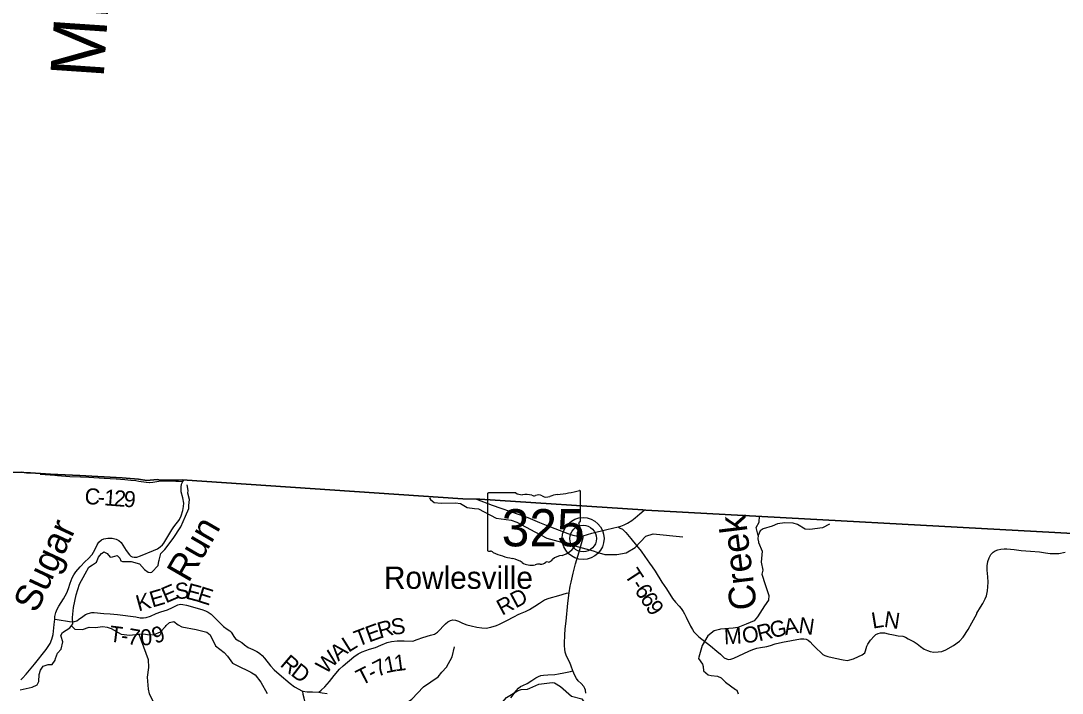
# Model space of a CAD drawing. Extents: x 1878108 to 2183446, y 146837 to 508383.
# Drawn here: x 2019382 to 2038879, y 364937 to 377520 of the extents above; entities that cross this region are included whole.
import ezdxf

# ---------------------------------------------------------------- set-up
doc = ezdxf.new("R2010")
doc.units = 0
for name, color, linetype in [('GM_X_Adjacent_County', 7, 'Continuous'), ('GM_X_Adjacent_County_Text', 7, 'Continuous'), ('GM_X_County', 7, 'Continuous'), ('GM_X_County_Road', 7, 'Continuous'), ('GM_X_County_Road_Text', 7, 'Continuous'), ('GM_X_Minor_River', 7, 'Continuous'), ('GM_X_Minor_River_Text', 7, 'Continuous'), ('GM_X_State_Location', 7, 'Continuous'), ('GM_X_State_Route', 7, 'Continuous'), ('GM_X_State_Shield', 7, 'Continuous'), ('GM_X_Township', 7, 'Continuous'), ('GM_X_Township_Road', 7, 'Continuous'), ('GM_X_Township_Road_Text', 7, 'Continuous'), ('GM_X_Unincorporated', 7, 'Continuous'), ('GM_X_Unincorporated_Location', 7, 'Continuous'), ('GM_X_Unincorporated_Text', 7, 'Continuous')]:
    doc.layers.add(name, color=color, linetype=linetype)

msp = doc.modelspace()

# ---------------------------------------------------------------- linework, layer by layer
at = {"layer": 'GM_X_Adjacent_County'}
msp.add_lwpolyline([(2039539, 367898), (2031084, 368365), (2031027, 368369), (2027978, 368566), (2027659, 368574), (2022405, 368932), (2022089, 368925), (2021996, 368922), (2021936, 368934), (2021744, 368917), (2021587, 368942), (2021277, 368968), (2020487, 369014), (2019939, 369039), (2019751, 369047), (2019564, 369063), (2019490, 369063), (2019394, 369075), (2018544, 369044)], dxfattribs=at)
at = {"layer": 'GM_X_County'}
msp.add_lwpolyline([(2018544, 369044), (2019394, 369075), (2019490, 369063), (2019564, 369063), (2019751, 369047), (2019939, 369039), (2020487, 369014), (2021277, 368968), (2021587, 368942), (2021744, 368917), (2021936, 368934), (2021996, 368922), (2022089, 368925), (2022405, 368932), (2027659, 368574), (2027978, 368566), (2031027, 368369), (2031084, 368365), (2039539, 367898)], dxfattribs=at)
at = {"layer": 'GM_X_County_Road'}
for points in [[(2019746, 369036), (2019930, 369022), (2020016, 369015), (2020069, 369011)], [(2020069, 369011), (2020301, 368994), (2020496, 368986), (2020657, 368979), (2020945, 368964), (2021167, 368947), (2021249, 368941), (2021330, 368934), (2021444, 368924), (2021532, 368915), (2021592, 368907), (2021731, 368884), (2021794, 368880), (2021797, 368881), (2021854, 368888), (2021964, 368904), (2022007, 368910), (2022091, 368912)], [(2022091, 368912), (2022094, 368912), (2022283, 368906), (2022286, 368906), (2022336, 368908), (2022414, 368900)], [(2029963, 364936), (2029955, 364991), (2029942, 365027), (2029920, 365065), (2029874, 365116), (2029818, 365168), (2029786, 365213), (2029754, 365267), (2029719, 365355), (2029687, 365442), (2029660, 365512), (2029622, 365582), (2029590, 365648), (2029573, 365706), (2029565, 365760), (2029561, 365825), (2029561, 365874), (2029565, 366025), (2029575, 366140), (2029592, 366287), (2029626, 366621), (2029648, 366813), (2029669, 366937), (2029685, 367016), (2029725, 367181), (2029768, 367361), (2029834, 367585), (2029910, 367852), (2029910, 367883)]]:
    msp.add_lwpolyline(points, dxfattribs=at)
at = {"layer": 'GM_X_Minor_River'}
for points in [[(2019368, 364997), (2019596, 365051), (2019686, 365094), (2019716, 365156), (2019725, 365284), (2019747, 365365), (2019803, 365443), (2019893, 365475), (2019969, 365473), (2020027, 365552), (2020033, 365586), (2020071, 365684), (2020137, 365762), (2020169, 365895), (2020135, 365999), (2020133, 366015), (2020161, 366073), (2020302, 366160), (2020356, 366238), (2020350, 366353), (2020366, 366543), (2020416, 366778), (2020480, 366975), (2020587, 367171), (2020655, 367294), (2020725, 367340), (2020801, 367389), (2020833, 367483), (2020891, 367551), (2020905, 367559), (2020937, 367581), (2021001, 367553), (2021057, 367481), (2021101, 367487), (2021185, 367512), (2021235, 367467), (2021257, 367415), (2021285, 367403), (2021449, 367404), (2021601, 367358), (2021695, 367254), (2021765, 367202), (2021807, 367196), (2021833, 367202), (2021951, 367326), (2021967, 367409), (2021971, 367429), (2022000, 367549), (2022080, 367627), (2022234, 367832), (2022380, 368051), (2022466, 368250), (2022525, 368395), (2022525, 368451), (2022539, 368559), (2022507, 368683), (2022513, 368730), (2022494, 368839)], [(2027034, 368594), (2027053, 368560), (2027120, 368506), (2027249, 368492), (2027520, 368502), (2027614, 368486), (2027739, 368412), (2027875, 368393), (2027953, 368385), (2028279, 368212), (2028564, 368174), (2028670, 368136), (2029005, 367957), (2029232, 367836), (2030097, 367602), (2030165, 367579), (2030317, 367531), (2030540, 367535), (2030717, 367565), (2030884, 367662), (2031083, 367873), (2031224, 367918), (2031776, 367865)], [(2034522, 368099), (2034391, 368031), (2034157, 367999), (2034067, 368009), (2033921, 368091), (2033845, 368117), (2033685, 368124), (2033547, 368106), (2033447, 368062), (2033281, 368013), (2033225, 367977), (2033185, 367891), (2033179, 367825), (2033193, 367770), (2033195, 367760), (2033260, 367596), (2033244, 367391), (2033272, 367237), (2033254, 367165), (2033320, 366974), (2033386, 366764), (2033378, 366679), (2033303, 366569), (2033173, 366364), (2033109, 366294), (2032965, 366231), (2032805, 366167), (2032717, 366155), (2032479, 366134), (2032465, 366130), (2032365, 366102), (2032247, 366013), (2032140, 365829), (2032074, 365608), (2032072, 365586), (2032144, 365478), (2032156, 365436), (2032164, 365353), (2032250, 365281), (2032308, 365267), (2032426, 365253), (2032496, 365227), (2032516, 365203), (2032576, 365141), (2032760, 365009), (2032790, 364993), (2032810, 364927)], [(2033185, 367891), (2033151, 368040), (2033207, 368140), (2033211, 368249)], [(2020328, 366197), (2020394, 366138), (2020538, 366130), (2020664, 366171), (2020774, 366167), (2020916, 366185), (2020998, 366173), (2021074, 366149), (2021260, 366041), (2021422, 366023), (2021576, 366040), (2021678, 366050), (2021790, 366028), (2021880, 366036), (2021996, 366087), (2022088, 366187), (2022102, 366201), (2022167, 366257), (2022245, 366278), (2022329, 366218), (2022395, 366180), (2022663, 366130), (2022867, 366078), (2022927, 366032), (2023029, 365826), (2023191, 365697), (2023253, 365627), (2023348, 365501), (2023422, 365461), (2023688, 365331), (2023706, 365321), (2023770, 365279), (2023874, 365143), (2023992, 364928)], [(2021593, 366041), (2021767, 365565), (2021771, 365419), (2021747, 365235), (2021763, 365012), (2021787, 364922), (2021897, 364708), (2022036, 364374), (2022176, 364186), (2022188, 364146), (2022254, 364104), (2022286, 364046)], [(2026531, 364214), (2026554, 364541), (2026586, 364679), (2026640, 364779), (2026702, 364823), (2026923, 365056), (2027195, 365245), (2027265, 365333), (2027349, 365423), (2027460, 365616), (2027500, 365802)], [(2027310, 363901), (2027426, 363865), (2027630, 363934), (2027768, 364060), (2027875, 364221), (2027951, 364365), (2028029, 364455), (2028121, 364498), (2028191, 364500), (2028269, 364588), (2028316, 364678), (2028478, 364855), (2028680, 364983), (2028750, 365003), (2028867, 365010), (2028913, 365032), (2029079, 365108), (2029329, 365139), (2029373, 365133), (2029483, 365063), (2029693, 364879), (2029885, 364831), (2029933, 364757), (2029963, 364657)]]:
    msp.add_lwpolyline(points, dxfattribs=at)
at = {"layer": 'GM_X_State_Route'}
for points in [[(2019379, 365187), (2019416, 365220), (2019484, 365292), (2019638, 365477), (2019855, 365752), (2019932, 365866), (2019964, 365945), (2019985, 366033), (2020005, 366224), (2020017, 366320), (2020021, 366375), (2020037, 366444), (2020062, 366509), (2020093, 366566), (2020181, 366703), (2020243, 366816), (2020276, 366897), (2020308, 366994), (2020344, 367096), (2020376, 367154), (2020414, 367209), (2020495, 367304), (2020589, 367399), (2020642, 367453), (2020715, 367535), (2020745, 367578), (2020779, 367644), (2020810, 367714), (2020842, 367763), (2020890, 367804), (2020938, 367826), (2021013, 367841), (2021093, 367840), (2021164, 367822), (2021217, 367797), (2021258, 367757), (2021292, 367710), (2021356, 367607), (2021414, 367527), (2021440, 367502), (2021468, 367486), (2021503, 367481), (2021551, 367485), (2021621, 367509), (2021864, 367607), (2021941, 367640), (2021993, 367673), (2022032, 367711), (2022061, 367746), (2022208, 367994), (2022233, 368033), (2022283, 368098), (2022322, 368147), (2022351, 368188), (2022381, 368256), (2022414, 368358), (2022428, 368434), (2022432, 368494), (2022413, 368593), (2022385, 368707), (2022383, 368792), (2022392, 368851), (2022414, 368900), (2022433, 368931)], [(2027914, 368569), (2028209, 368454), (2028715, 368281), (2028874, 368222), (2029092, 368134), (2029217, 368083), (2029622, 367923), (2029720, 367896), (2029778, 367884), (2029836, 367879), (2029910, 367883), (2030074, 367931), (2030355, 368003), (2030565, 368053), (2030615, 368065), (2030678, 368086), (2030739, 368117), (2030819, 368171), (2030884, 368220), (2030969, 368292), (2031051, 368365)]]:
    msp.add_lwpolyline(points, dxfattribs=at)
at = {"layer": 'GM_X_State_Shield'}
for p, q in [((2029861, 368159), (2029861, 368711)), ((2028121, 368667), (2028121, 367610)), ((2028648, 368685), (2028138, 368685)), ((2029861, 368159), (2029861, 368159))]:
    msp.add_line(p, q, dxfattribs=at)
for centre, major_axis, start_param, end_param in [((2029242, 370126), (1845, 0), 4.814394, 5.042369), ((2029842, 368714), (19.4, 0), 6.141152, 7.989035), ((2028141, 368669), (20.2, 0), 1.712693, 3.28349), ((2028769, 368808), (196, 0), 4.042523, 4.731795), ((2028834, 368092), (702, 0), 1.404758, 1.657858), ((2028994, 368675), (56.4, 0), 3.836095, 5.185415), ((2029076, 368553), (117, 0), 0.950623, 2.079405), ((2029228, 368720), (141, 0), 4.081561, 5.145723), ((2029477, 368363), (371, 0), 1.699011, 2.107814), ((2029857, 368118), (30, 0), 1.883978, 3.671073), ((2029841, 368157), (20.7, 0), 5.05454, 6.418171), ((2029345, 367857), (462, 0), 5.101752, 6.440018), ((2029931, 367927), (131, 0), 2.387724, 3.262537), ((2029666, 368048), (180, 0), 5.934695, 6.695948), ((2028141, 367608), (20.3, 0), 3.00124, 4.508301), ((2028144, 367716), (155, 0), 4.665946, 4.897461), ((2028176, 367549), (56, 0), 0.519207, 1.627899), ((2028883, 368499), (1333, 0), 4.195997, 4.488961), ((2028485, 367136), (417, 0), 0.823519, 1.323587), ((2028936, 367544), (265, 0), 4.026481, 4.996735), ((2029089, 367179), (217, 0), 1.495662, 1.94098), ((2029109, 367465), (141, 0), 4.691044, 5.507374), ((2029236, 367363), (39.7, 0), 1.147584, 2.315152), ((2029219, 367508), (149, 0), 4.937069, 5.64225), ((2029540, 367314), (253, 0), 1.647645, 2.488434)]:
    msp.add_ellipse(centre, major_axis=major_axis, ratio=0.8, start_param=start_param, end_param=end_param, dxfattribs=at)
at = {"layer": 'GM_X_Township'}
msp.add_lwpolyline([(2018544, 369044), (2019394, 369075), (2019490, 369063), (2019564, 369063), (2019751, 369047), (2019939, 369039), (2020487, 369014), (2021277, 368968), (2021587, 368942), (2021744, 368917), (2021936, 368934), (2021996, 368922), (2022089, 368925), (2022405, 368932), (2027659, 368574), (2027978, 368566), (2031027, 368369), (2031084, 368365), (2039539, 367898)], dxfattribs=at)
at = {"layer": 'GM_X_Township_Road'}
for points in [[(2030565, 368053), (2030603, 368027), (2030645, 368009), (2030710, 367943), (2030800, 367833), (2030910, 367698), (2030997, 367594), (2031067, 367496), (2031155, 367368), (2031204, 367302), (2031256, 367222), (2031383, 367012), (2031469, 366887), (2031583, 366707), (2031637, 366639), (2031707, 366565), (2031745, 366519), (2031780, 366467), (2031805, 366425), (2031840, 366358), (2031919, 366194), (2031955, 366126), (2031983, 366084), (2032025, 366040), (2032079, 365989), (2032293, 365822), (2032416, 365725), (2032479, 365668), (2032518, 365628), (2032552, 365598), (2032595, 365578), (2032632, 365570), (2032677, 365571), (2032733, 365591), (2033010, 365722), (2033086, 365754), (2033160, 365777), (2033229, 365793), (2033351, 365810), (2033419, 365828), (2033506, 365858), (2033641, 365889), (2033978, 365955), (2034039, 365957), (2034086, 365946), (2034125, 365927), (2034161, 365895), (2034213, 365842), (2034281, 365774), (2034363, 365699), (2034399, 365664), (2034435, 365645), (2034492, 365626), (2034626, 365594), (2034776, 365564), (2034859, 365551), (2034906, 365559), (2034971, 365582), (2035064, 365624), (2035134, 365656), (2035185, 365692), (2035198, 365727), (2035223, 365814), (2035239, 365857), (2035292, 365928), (2035356, 366006), (2035392, 366035), (2035432, 366053), (2035476, 366064), (2035510, 366065), (2035536, 366064)], [(2037279, 366425), (2037282, 366432), (2037349, 366550), (2037392, 366614), (2037440, 366703), (2037463, 366761), (2037480, 366851), (2037490, 366928), (2037493, 367014), (2037486, 367114), (2037477, 367240), (2037477, 367320), (2037487, 367402), (2037509, 367471), (2037541, 367532), (2037584, 367576), (2037625, 367599), (2037672, 367617), (2037728, 367630), (2037794, 367638), (2037844, 367637), (2037978, 367624), (2038110, 367610), (2038286, 367598), (2038455, 367582), (2038569, 367564), (2038655, 367552), (2038744, 367549), (2038816, 367554), (2038933, 367575)], [(2024960, 364955), (2025002, 364993), (2025071, 365058), (2025159, 365154), (2025250, 365268), (2025349, 365387), (2025419, 365452), (2025615, 365618), (2025699, 365675), (2025773, 365711), (2025911, 365759), (2026023, 365794), (2026123, 365836), (2026243, 365884), (2026322, 365905), (2026426, 365916), (2026562, 365917), (2026720, 365911), (2026801, 365940), (2026907, 365980), (2027054, 366020), (2027125, 366041), (2027181, 366079), (2027230, 366128), (2027285, 366185), (2027331, 366234), (2027375, 366271), (2027425, 366297), (2027471, 366307), (2027521, 366303), (2027577, 366285), (2027654, 366250), (2027735, 366215), (2027815, 366195), (2027921, 366173), (2028015, 366160), (2028096, 366156), (2028182, 366171), (2028289, 366202), (2028347, 366227), (2028471, 366293), (2028624, 366373), (2028691, 366407), (2028738, 366428), (2028831, 366465), (2028906, 366503), (2029004, 366567), (2029095, 366624), (2029187, 366682), (2029273, 366717), (2029455, 366765), (2029601, 366807), (2029648, 366813)], [(2021619, 366348), (2021630, 366346), (2021681, 366346), (2021727, 366354), (2021812, 366381), (2021915, 366426), (2022005, 366460), (2022131, 366494), (2022220, 366538), (2022321, 366588), (2022369, 366600), (2022415, 366599), (2022484, 366585), (2022768, 366502), (2022840, 366479), (2022891, 366452), (2022946, 366416), (2023010, 366354), (2023149, 366209), (2023178, 366184), (2023248, 366138), (2023294, 366106), (2023319, 366076)], [(2020017, 366320), (2020064, 366319), (2020290, 366281), (2020344, 366274), (2020385, 366276), (2020428, 366291), (2020463, 366313), (2020544, 366373), (2020595, 366407), (2020640, 366429), (2020710, 366448), (2020757, 366449), (2020937, 366430), (2021055, 366423), (2021193, 366408), (2021534, 366364), (2021619, 366348)], [(2035536, 366064), (2035553, 366064), (2035620, 366049), (2035718, 366028), (2035809, 366012), (2035894, 366002), (2035946, 365987), (2035998, 365957), (2036105, 365895), (2036165, 365863), (2036227, 365812), (2036294, 365760), (2036355, 365733), (2036410, 365716), (2036477, 365707), (2036560, 365711), (2036626, 365720), (2036702, 365751), (2036842, 365832), (2036958, 365908), (2037026, 365986), (2037116, 366129), (2037187, 366252), (2037279, 366425)], [(2023319, 366076), (2023335, 366059), (2023371, 365996), (2023404, 365955), (2023464, 365915), (2023520, 365884), (2023571, 365843), (2023641, 365793), (2023727, 365755), (2023803, 365718), (2023852, 365684)], [(2023852, 365684), (2023854, 365682), (2023898, 365642), (2023941, 365594), (2024055, 365450), (2024128, 365376), (2024217, 365295), (2024424, 365121), (2024506, 365054), (2024584, 365011), (2024641, 364983), (2024664, 364975), (2024742, 364963), (2024843, 364960), (2024960, 364955), (2025025, 364944), (2025115, 364929)], [(2028556, 364850), (2028655, 364980), (2028702, 365030), (2028740, 365060), (2028778, 365081), (2028859, 365119), (2028947, 365177), (2029024, 365225), (2029076, 365251), (2029116, 365268), (2029168, 365277), (2029250, 365281), (2029381, 365289), (2029449, 365297), (2029547, 365317), (2029675, 365345), (2029719, 365355)], [(2025078, 363190), (2025063, 363208), (2025015, 363289), (2025001, 363345), (2024980, 363495), (2024961, 363693), (2024954, 363743), (2024932, 363807), (2024890, 363927), (2024839, 364056), (2024786, 364188), (2024768, 364247), (2024752, 364319), (2024753, 364386), (2024758, 364480), (2024748, 364589), (2024714, 364731), (2024686, 364842), (2024668, 364911), (2024664, 364975)]]:
    msp.add_lwpolyline(points, dxfattribs=at)
at = {"layer": 'GM_X_Unincorporated'}
for radius in [393, 249]:
    msp.add_circle((2029909, 367831), radius, dxfattribs=at)
at = {"layer": 'GM_X_Unincorporated_Location'}
msp.add_line((2029909, 367831), (2029909, 367831), dxfattribs=at)

# ---------------------------------------------------------------- texts
at = {"layer": 'GM_X_Adjacent_County_Text'}
msp.add_text('MEIGS COUNTY', height=1000, rotation=86.1364, dxfattribs=at).set_placement((2020930, 376428))
at = {"layer": 'GM_X_County_Road_Text'}
for s, rotation, p in [('C', 355.7438, (2020568, 368481)), ('1', 355.7442, (2020934, 368454)), ('2', 355.7486, (2021117, 368440)), ('9', 355.7685, (2021300, 368427)), ('-', 355.7439, (2020812, 368463))]:
    msp.add_text(s, height=300, rotation=rotation, dxfattribs=at).set_placement(p)
at = {"layer": 'GM_X_Minor_River_Text'}
for s, height, rotation, p in [('Sugar', 500.1, 65.0058, (2019675, 366419)), ('Run', 500, 60.0068, (2022522, 366987)), ('Creek', 500.1, 97.0003, (2033165, 366522))]:
    msp.add_text(s, height=height, rotation=rotation, dxfattribs=at).set_placement(p)
at = {"layer": 'GM_X_State_Location'}
msp.add_text('325', height=1, rotation=0, dxfattribs=at).set_placement((2028619, 367996))
for s in ['s', 'r']:
    msp.add_text(s, height=1, dxfattribs=at).set_placement((2028972, 368068))
at = {"layer": 'GM_X_State_Shield'}
msp.add_text('325', height=696.1, dxfattribs=at).set_placement((2028385, 367685))
at = {"layer": 'GM_X_Township_Road_Text'}
for s, rotation, p in [('T', 303.0494, (2030673, 367151)), ('E', 23.2624, (2022097, 366615)), ('S', 3.6374, (2022276, 366697)), ('E', 345.0636, (2022453, 366713)), ('-', 303.0692, (2030795, 366963)), ('6', 303.1509, (2030863, 366860)), ('K', 15.2909, (2021584, 366467)), ('E', 16.3321, (2021844, 366538)), ('E', 342.5192, (2022666, 366656)), ('RD', 28.2677, (2028393, 366383)), ('6', 303.4382, (2030965, 366704)), ('9', 304.2835, (2031069, 366545)), ('N', 351.6654, (2033930, 366067)), ('L', 9.4278, (2035334, 366144)), ('N', 351.4258, (2035531, 366180)), ('T', 352.6427, (2021024, 365907)), ('9', 19.9065, (2021899, 365858)), ('T', 20.9212, (2025693, 365804)), ('E', 19.9923, (2025901, 365883)), ('R', 15.8124, (2026106, 365958)), ('S', 7.8889, (2026333, 366023)), ('M', 2.4139, (2032552, 365851)), ('O', 7.2185, (2032905, 365867)), ('R', 13.6748, (2033203, 365906)), ('G', 12.3866, (2033440, 365964)), ('A', 10.2097, (2033695, 366020)), ('-', 352.3435, (2021246, 365878)), ('7', 349.9884, (2021365, 365862)), ('0', 4.1801, (2021628, 365826)), ('L', 32.3016, (2025517, 365691)), ('A', 40.821, (2025327, 365525)), ('R', 319.4423, (2024219, 365455)), ('W', 46.6083, (2025094, 365278)), ('7', 26.7745, (2026067, 365232)), ('1', 11.1711, (2026212, 365309)), ('1', 7.6201, (2026388, 365344)), ('D', 322.3957, (2024419, 365284)), ('T', 26.9637, (2025757, 365075)), ('-', 26.9351, (2025957, 365177))]:
    msp.add_text(s, height=300, rotation=rotation, dxfattribs=at).set_placement(p)
at = {"layer": 'GM_X_Unincorporated_Text'}
msp.add_text('Rowlesville', height=417, rotation=0, dxfattribs=at).set_placement((2026181, 366890))

doc.saveas('drawing.dxf')
